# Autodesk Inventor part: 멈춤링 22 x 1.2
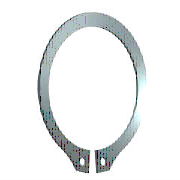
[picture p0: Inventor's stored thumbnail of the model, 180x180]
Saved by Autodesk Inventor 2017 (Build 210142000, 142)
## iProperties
IsCustomPart: 0
Created: 2021-07
Part Number: 멈춤링 22 x 1.2
Material: 강철, 연강
Description: 리테이닝 링(C형)
Document SubType Name: Modeling
Standard: KS B 1336
Designer: mdu
Standards Organization: KS
Language: ko-KR
Size Designation: 22 x 1.2
Categories: <MemberInstance><Categories><Category DisplayName="샤프트 부품" InternalName="7f7aeb1f-a693-4053-b835-cee3144e0d98" Mnemonic="SHFT"><Category DisplayName="써클립" Inter
Density: 7.86 g/cm^3
Mass: 1.8286 g
Surface Area: 5.91219 cm^2
Volume: 0.232646 cm^3
Appearance: 파란색 - 벽 페인트 - 광택
Author: mdu
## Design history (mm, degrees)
sketch "스케치1"
  geometry: L1 (-6, 0)-(6, 0) reference; L2 (0, 20.189)-(0, -80.536) reference; L3 (-48.09, 0)-(48.09, 0) reference; L4 (-0.5, -21.488)-(-0.5, -25.588); L5 (-0.5, -6.54)-(-0.5, -13.29); L6 (-2.795, 2.7)-(3.672, 2.7); L7 (0.5, -6.54)-(0.5, -13.29); L8 (0.5, -21.488)-(0.5, -25.588); C1 r 1 at (-2, -23.437); C2 r 1 at (2, -23.437); A1 r 10.5 centre (0, -11) between (0.5, -21.488) and (-0.5, -21.488); A2 r 13.025 centre (0, -10.325) between (5.149, -22.289) and (-5.149, -22.289); A3 r 14.597 centre (0, -11) between (-2.318, -25.411) and (-0.5, -25.588); A4 r 2 centre (-2, -23.437) between (-3.97, -23.781) and (-2.318, -25.411); A5 r 2 centre (-5.94, -24.126) between (-3.97, -23.781) and (-5.149, -22.289); A6 r 2 centre (5.94, -24.126) between (5.149, -22.289) and (3.97, -23.781); A7 r 2 centre (2, -23.437) between (2.318, -25.411) and (3.97, -23.781); A8 r 14.597 centre (0, -11) between (0.5, -25.588) and (2.318, -25.411)
  constraints: 16 point on circle, 12 end point, 10 centre point, 9 symmetric about line, 5 point on line, 4 tangent, 3 coincident, 2 horizontal, 1 perpendicular, 1 vertical, 5 other
  dimensions: "d0" = 21 diameter of A1 (= ND); "d1" = 4.1 distance of L4.end L4.start (= SRB2); "d6" = 0.5 distance between parallel lines of L2 L5 (= 0.25 x SD5); "d7" = 2.7 distance between parallel lines of L6 L3 (= SRB1); "d8" = 0.675 distance of A1.centre A2.centre (= 0.25 x SRB1); "d9" = 2 radius of A4 (= SD5); "d10" = 2 radius of A5 (= SD5); "d11" = 1.5 distance from line of L4 A4.centre (= 0.75 x SD5); "d12" = 2 diameter of C1 (= SD5); "d13" = 2 diameter of C2 (= SD5); "d14" = 11 distance from line of A1.centre L1 (= 0.5 x WD)
extrude "본체" new body sketch "스케치1" distance "d2" = 1.2 (= SD); taper "d3" = 0 deg
workaxis "Work Axis1"
workplane "Work Plane1"
body "Solid1"
other parameters: "WD" = 22 (= WDMIN) [user parameter; used in 1 equation term], "SD" = 1.2 [user parameter; used in 1 equation term], "SRB1" = 2.7 [user parameter; used in 2 equation terms], "ND" = 21 [user parameter; used in 1 equation term], "SRB2" = 4.1 [user parameter; used in 1 equation term], "SD5" = 2 [user parameter; used in 6 equation terms], "d15" = 0, "d16" = 0, "d17" = 0, "d41" = 0, "d42" = 0, "WDMIN" = 22 [user parameter; used in 1 equation term], "SD3" = 20.5 [user parameter], "WDMAX" = 24 [user parameter]
